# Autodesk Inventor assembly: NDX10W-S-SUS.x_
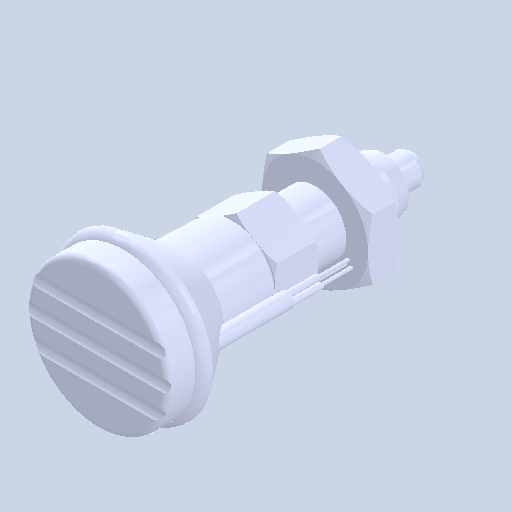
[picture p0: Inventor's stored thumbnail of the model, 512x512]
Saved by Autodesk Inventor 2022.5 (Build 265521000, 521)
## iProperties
Created: 2024-05
Part Number: NDX10W-S-SUS.x_
Document SubType Name: Assembly
Designer: ImaoCorp
Author: ImaoCorp
Sending System: SOLIDWORKS 2022-2022290
MC: AMD64
MC_MODEL: Intel64 Family 6 Model 60 Stepping 3, GenuineIntel
OS: Windows_NT
FRU: Parasolid Version 33.1, build 260,  4-25-2022
FORMAT: text
GUISE: transmit
KEY: FILENDX10W-S-SUS.x_t
DATE: Tue May 21 08:48:00 2024
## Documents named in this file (3)
- X:\14_SW2022-Inv2022\保留中\kipp\KME_データ\n\ndx10w-s-sus\NDX10W-S-SUS.x_.iam
- X:\14_SW2022-Inv2022\保留中\kipp\KME_データ\n\ndx10w-s-sus\NDX10W-S-SUS_01.ipt
- X:\14_SW2022-Inv2022\保留中\kipp\KME_データ\n\ndx10w-s-sus\NDX10W-S-SUS_02.ipt
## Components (2 placed, 2 different names)
1. NDX10W-S-SUS_01
2. NDX10W-S-SUS_02
